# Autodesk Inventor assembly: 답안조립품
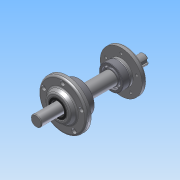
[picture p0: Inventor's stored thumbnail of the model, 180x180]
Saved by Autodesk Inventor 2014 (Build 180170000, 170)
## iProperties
Created: 2015-08
Part Number: 답안조립품
Document SubType Name: Assembly
Designer: study
Author: study
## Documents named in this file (9)
- C:\Users\study\Desktop\450805V1022\답안조립품.iam
- C:\Users\study\Desktop\450805V1022\1-본체.ipt
- C:\Users\study\Desktop\450805V1022\베어링 6203.ipt
- C:\Users\study\Desktop\450805V1022\베어링 6205.ipt
- C:\Users\study\Desktop\450805V1022\뒤커버.ipt
- C:\Users\study\Desktop\450805V1022\앞커버.ipt
- C:\Users\study\Desktop\450805V1022\오일실 .ipt
- 오일실 .ipt
- C:\Users\study\Desktop\450805V1022\축.ipt
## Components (1 placed, 1 different names)
1. 1-본체:1
